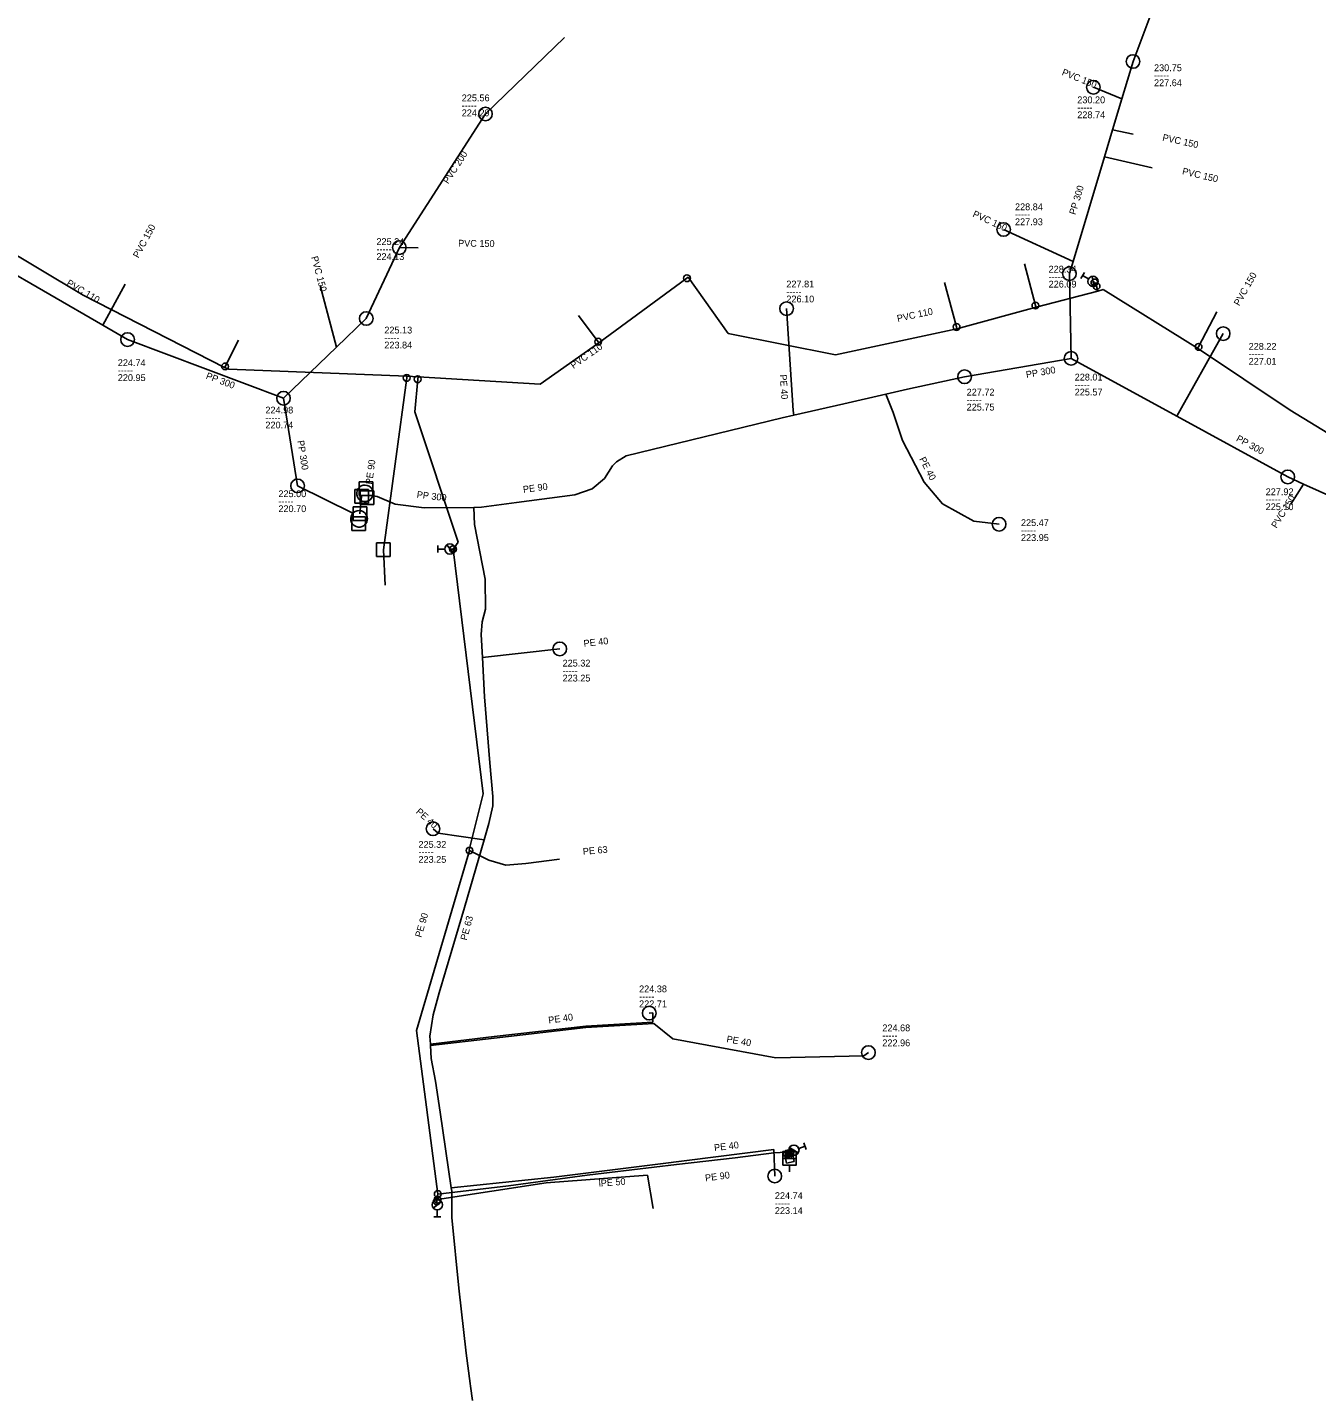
# Model space of a CAD drawing. Extents: x -771542 to -770341, y -1050442 to -1049881.
# Drawn here: x -770940.3 to -770751, y -1050441.5 to -1050239.8 of the extents above; entities that cross this region are included whole.
import ezdxf

# ---------------------------------------------------------------- set-up
doc = ezdxf.new("R2010")
doc.units = 0
doc.layers.add('Level 0', color=7, linetype='Continuous')

msp = doc.modelspace()

# ---------------------------------------------------------------- linework, layer by layer
at = {"layer": 'Level 0'}
for p, q in [((-770775.11, -1050237.31), (-770777.92, -1050244.75)), ((-770873.03, -1050252.46), (-770861.42, -1050241.24)), ((-770777.92, -1050244.75), (-770779.56, -1050250.23)), ((-770779.56, -1050250.23), (-770783.75, -1050248.53)), ((-770779.56, -1050250.23), (-770780.93, -1050254.79)), ((-770873.03, -1050252.46), (-770885.68, -1050272.1)), ((-770971.95, -1050255.18), (-770932.14, -1050279.1)), ((-770780.93, -1050254.79), (-770782.12, -1050258.77)), ((-770780.93, -1050254.79), (-770777.92, -1050255.44)), ((-770782.12, -1050258.77), (-770786.73, -1050274.16)), ((-770782.12, -1050258.77), (-770775.1, -1050260.4)), ((-770786.73, -1050274.16), (-770796.93, -1050269.44)), ((-770948.76, -1050272.21), (-770929.23, -1050283.51)), ((-770885.68, -1050272.1), (-770890.55, -1050282.52)), ((-770885.68, -1050272.1), (-770882.93, -1050272.13)), ((-770792.26, -1050280.61), (-770793.88, -1050274.5)), ((-770786.73, -1050274.16), (-770787.26, -1050275.93)), ((-770929.23, -1050283.51), (-770925.95, -1050277.46)), ((-770894.93, -1050286.74), (-770897.33, -1050277.68)), ((-770843.44, -1050276.6), (-770856.36, -1050286.09)), ((-770843.24, -1050276.45), (-770843.44, -1050276.6)), ((-770837.37, -1050284.72), (-770843.24, -1050276.45)), ((-770803.84, -1050283.76), (-770805.6, -1050277.24)), ((-770787.26, -1050275.93), (-770787.03, -1050288.38)), ((-770785.57, -1050276.62), (-770785.07, -1050275.75)), ((-770784.45, -1050276.69), (-770785.32, -1050276.19)), ((-770783.69, -1050277.8), (-770783.91, -1050276.32)), ((-770783.8, -1050277.06), (-770783.59, -1050277.22)), ((-770783.59, -1050277.22), (-770783.28, -1050277.78)), ((-770932.14, -1050279.1), (-770911.37, -1050289.74)), ((-770783.09, -1050278.48), (-770792.17, -1050280.85)), ((-770783.28, -1050277.78), (-770783.09, -1050278.48)), ((-770782.33, -1050278.28), (-770783.09, -1050278.48)), ((-770768.47, -1050286.88), (-770782.33, -1050278.28)), ((-770828.67, -1050283.24), (-770828.81, -1050281.07)), ((-770792.17, -1050280.85), (-770803.78, -1050284.02)), ((-770792.17, -1050280.85), (-770792.26, -1050280.61)), ((-770768.3, -1050286.69), (-770765.63, -1050281.52)), ((-770929.23, -1050283.51), (-770925.6, -1050285.61)), ((-770890.55, -1050282.52), (-770894.93, -1050286.74)), ((-770856.48, -1050285.93), (-770859.37, -1050282.07)), ((-770827.86, -1050296.04), (-770828.67, -1050283.24)), ((-770925.6, -1050285.61), (-770902.7, -1050294.23)), ((-770911.28, -1050289.56), (-770909.32, -1050285.69)), ((-770821.6, -1050287.84), (-770837.37, -1050284.72)), ((-770803.78, -1050284.02), (-770821.6, -1050287.84)), ((-770803.78, -1050284.02), (-770803.84, -1050283.76)), ((-770771.51, -1050296.87), (-770764.68, -1050284.74)), ((-770894.93, -1050286.74), (-770902.7, -1050294.23)), ((-770856.36, -1050286.09), (-770865.02, -1050292.18)), ((-770856.36, -1050286.09), (-770856.48, -1050285.93)), ((-770768.47, -1050286.88), (-770768.3, -1050286.69)), ((-770754.83, -1050296.01), (-770768.47, -1050286.88)), ((-770911.37, -1050289.74), (-770911.28, -1050289.56)), ((-770911.37, -1050289.74), (-770910.71, -1050289.96)), ((-770802.67, -1050291.08), (-770787.03, -1050288.38)), ((-770787.03, -1050288.38), (-770771.51, -1050296.87)), ((-770910.71, -1050289.96), (-770884.6, -1050290.99)), ((-770884.6, -1050291.25), (-770888.02, -1050316.5)), ((-770884.6, -1050290.99), (-770884.6, -1050291.25)), ((-770884.6, -1050290.99), (-770882.93, -1050291.09)), ((-770882.99, -1050291.44), (-770883.43, -1050296.23)), ((-770882.93, -1050291.09), (-770882.99, -1050291.44)), ((-770865.02, -1050292.18), (-770882.93, -1050291.09)), ((-770811.05, -1050292.89), (-770802.67, -1050291.08)), ((-770820.42, -1050295.05), (-770814.21, -1050293.62)), ((-770814.21, -1050293.62), (-770811.05, -1050292.89)), ((-770813.13, -1050296.32), (-770814.21, -1050293.62)), ((-770902.7, -1050294.23), (-770900.64, -1050307.11)), ((-770827.72, -1050296.72), (-770820.42, -1050295.05)), ((-770883.43, -1050296.23), (-770877.05, -1050315.4)), ((-770852.35, -1050302.69), (-770829.48, -1050297.12)), ((-770829.48, -1050297.12), (-770827.72, -1050296.72)), ((-770827.72, -1050296.72), (-770827.86, -1050296.04)), ((-770811.78, -1050300.44), (-770813.13, -1050296.32)), ((-770771.51, -1050296.87), (-770755.19, -1050305.8)), ((-770727.47, -1050312.73), (-770754.83, -1050296.01)), ((-770808.61, -1050306.59), (-770811.78, -1050300.44)), ((-770854.38, -1050304.17), (-770853.77, -1050303.58)), ((-770853.77, -1050303.58), (-770852.35, -1050302.69)), ((-770855.53, -1050306.02), (-770854.38, -1050304.17)), ((-770755.19, -1050305.8), (-770752.89, -1050306.84)), ((-770900.64, -1050307.11), (-770892.51, -1050311.14)), ((-770890.23, -1050307.66), (-770892.23, -1050307.66)), ((-770892.23, -1050307.66), (-770892.23, -1050309.66)), ((-770891.89, -1050307.82), (-770891.95, -1050308.13)), ((-770891.76, -1050307.54), (-770891.89, -1050307.82)), ((-770891.56, -1050307.3), (-770891.76, -1050307.54)), ((-770889.6, -1050306.53), (-770891.6, -1050306.53)), ((-770891.6, -1050306.53), (-770891.6, -1050308.53)), ((-770891.3, -1050307.13), (-770891.56, -1050307.3)), ((-770889.45, -1050307.84), (-770891.45, -1050307.84)), ((-770891.45, -1050307.84), (-770891.45, -1050309.84)), ((-770891.01, -1050307.02), (-770891.3, -1050307.13)), ((-770890.7, -1050306.99), (-770891.01, -1050307.02)), ((-770890.39, -1050307.04), (-770890.7, -1050306.99)), ((-770890.1, -1050307.17), (-770890.39, -1050307.04)), ((-770890.23, -1050309.66), (-770890.23, -1050307.66)), ((-770889.86, -1050307.36), (-770890.1, -1050307.17)), ((-770889.67, -1050307.61), (-770889.86, -1050307.36)), ((-770889.56, -1050307.9), (-770889.67, -1050307.61)), ((-770889.6, -1050308.53), (-770889.6, -1050306.53)), ((-770889.52, -1050308.21), (-770889.56, -1050307.9)), ((-770889.45, -1050309.84), (-770889.45, -1050307.84)), ((-770859.9, -1050308.42), (-770857.38, -1050307.53)), ((-770857.38, -1050307.53), (-770855.53, -1050306.02)), ((-770805.89, -1050309.75), (-770808.61, -1050306.59)), ((-770752.89, -1050306.84), (-770754.72, -1050309.79)), ((-770752.89, -1050306.84), (-770738.6, -1050313.34)), ((-770892.23, -1050309.66), (-770890.23, -1050309.66)), ((-770891.95, -1050308.13), (-770891.93, -1050308.44)), ((-770891.93, -1050308.44), (-770891.84, -1050308.74)), ((-770891.84, -1050308.74), (-770891.67, -1050309)), ((-770891.67, -1050309), (-770891.44, -1050309.21)), ((-770891.6, -1050308.53), (-770889.6, -1050308.53)), ((-770891.47, -1050311.21), (-770891.23, -1050308.66)), ((-770891.45, -1050309.84), (-770889.45, -1050309.84)), ((-770891.44, -1050309.21), (-770891.16, -1050309.35)), ((-770891.16, -1050309.35), (-770890.86, -1050309.42)), ((-770890.86, -1050309.42), (-770890.55, -1050309.41)), ((-770890.55, -1050309.41), (-770890.25, -1050309.32)), ((-770890.25, -1050309.32), (-770889.98, -1050309.16)), ((-770889.98, -1050309.16), (-770889.76, -1050308.94)), ((-770889.76, -1050308.53), (-770888.96, -1050308.68)), ((-770889.76, -1050308.94), (-770889.61, -1050308.67)), ((-770889.61, -1050308.67), (-770889.53, -1050308.37)), ((-770889.53, -1050308.37), (-770889.52, -1050308.21)), ((-770888.96, -1050308.68), (-770886.31, -1050309.82)), ((-770886.31, -1050309.82), (-770882.06, -1050310.32)), ((-770873.64, -1050310.22), (-770868.47, -1050309.54)), ((-770868.47, -1050309.54), (-770859.9, -1050308.42)), ((-770801.32, -1050312.29), (-770805.89, -1050309.75)), ((-770892.77, -1050311.56), (-770892.83, -1050311.87)), ((-770892.83, -1050311.87), (-770892.81, -1050312.18)), ((-770892.63, -1050311.28), (-770892.77, -1050311.56)), ((-770890.68, -1050311.65), (-770892.68, -1050311.65)), ((-770892.68, -1050311.65), (-770892.68, -1050313.65)), ((-770892.42, -1050311.05), (-770892.63, -1050311.28)), ((-770890.47, -1050310.21), (-770892.47, -1050310.21)), ((-770892.47, -1050310.21), (-770892.47, -1050312.21)), ((-770892.17, -1050310.87), (-770892.42, -1050311.05)), ((-770891.87, -1050310.76), (-770892.17, -1050310.87)), ((-770891.56, -1050310.74), (-770891.87, -1050310.76)), ((-770891.25, -1050310.79), (-770891.56, -1050310.74)), ((-770890.97, -1050310.91), (-770891.25, -1050310.79)), ((-770890.72, -1050311.11), (-770890.97, -1050310.91)), ((-770890.54, -1050311.36), (-770890.72, -1050311.11)), ((-770890.68, -1050313.65), (-770890.68, -1050311.65)), ((-770890.42, -1050311.65), (-770890.54, -1050311.36)), ((-770890.47, -1050312.21), (-770890.47, -1050310.21)), ((-770890.38, -1050311.96), (-770890.42, -1050311.65)), ((-770890.39, -1050312.14), (-770890.38, -1050311.96)), ((-770882.06, -1050310.32), (-770874.75, -1050310.3)), ((-770874.75, -1050310.3), (-770873.64, -1050310.22)), ((-770874.65, -1050312.8), (-770874.75, -1050310.3)), ((-770892.81, -1050312.18), (-770892.72, -1050312.48)), ((-770892.72, -1050312.48), (-770892.55, -1050312.74)), ((-770892.68, -1050313.65), (-770890.68, -1050313.65)), ((-770892.55, -1050312.74), (-770892.32, -1050312.96)), ((-770892.47, -1050312.21), (-770890.47, -1050312.21)), ((-770892.32, -1050312.96), (-770892.05, -1050313.1)), ((-770892.05, -1050313.1), (-770891.74, -1050313.18)), ((-770891.74, -1050313.18), (-770891.43, -1050313.17)), ((-770891.43, -1050313.17), (-770891.13, -1050313.09)), ((-770891.13, -1050313.09), (-770890.86, -1050312.93)), ((-770890.86, -1050312.93), (-770890.64, -1050312.71)), ((-770890.64, -1050312.71), (-770890.48, -1050312.44)), ((-770890.48, -1050312.44), (-770890.39, -1050312.14)), ((-770873.1, -1050320.84), (-770874.65, -1050312.8)), ((-770797.59, -1050312.75), (-770801.32, -1050312.29)), ((-770887.02, -1050315.5), (-770889.02, -1050315.5)), ((-770889.02, -1050315.5), (-770889.02, -1050317.5)), ((-770887.02, -1050317.5), (-770887.02, -1050315.5)), ((-770880.01, -1050316.89), (-770880.01, -1050315.89)), ((-770877.8, -1050316.98), (-770878.72, -1050315.8)), ((-770877.05, -1050315.4), (-770877.8, -1050316.42)), ((-770889.02, -1050317.5), (-770887.02, -1050317.5)), ((-770888.02, -1050316.5), (-770887.79, -1050321.68)), ((-770879.01, -1050316.39), (-770880.01, -1050316.39)), ((-770877.8, -1050316.42), (-770878.26, -1050316.39)), ((-770877.8, -1050316.42), (-770873.36, -1050352.39)), ((-770873.04, -1050325.23), (-770873.1, -1050320.84)), ((-770873.53, -1050327.07), (-770873.04, -1050325.23)), ((-770873.65, -1050328.95), (-770873.53, -1050327.07)), ((-770873.47, -1050332.35), (-770873.65, -1050328.95)), ((-770873.47, -1050332.35), (-770862.12, -1050331.07)), ((-770873.17, -1050338.09), (-770873.47, -1050332.35)), ((-770872.39, -1050347.81), (-770873.17, -1050338.09)), ((-770871.95, -1050352.75), (-770872.39, -1050347.81)), ((-770873.36, -1050352.39), (-770875.44, -1050360.6)), ((-770872.54, -1050356.71), (-770871.94, -1050354.15)), ((-770871.94, -1050354.15), (-770871.95, -1050352.75)), ((-770880, -1050358.16), (-770880.74, -1050357.5)), ((-770873.24, -1050359.13), (-770880, -1050358.16)), ((-770873.24, -1050359.13), (-770872.54, -1050356.71)), ((-770876.12, -1050369.07), (-770873.24, -1050359.13)), ((-770875.38, -1050360.69), (-770883.16, -1050387.13)), ((-770875.44, -1050360.6), (-770875.38, -1050360.69)), ((-770875.38, -1050360.69), (-770872.54, -1050362.13)), ((-770872.54, -1050362.13), (-770870.04, -1050362.87)), ((-770867.13, -1050362.61), (-770862.14, -1050361.99)), ((-770870.04, -1050362.87), (-770867.13, -1050362.61)), ((-770879.83, -1050381.61), (-770876.12, -1050369.07)), ((-770880.7, -1050384.86), (-770879.83, -1050381.61)), ((-770848.46, -1050384.57), (-770848.98, -1050384.59)), ((-770848.43, -1050385.94), (-770848.46, -1050384.57)), ((-770881.19, -1050388), (-770880.7, -1050384.86)), ((-770871.76, -1050388.05), (-770858.31, -1050386.52)), ((-770858.31, -1050386.52), (-770848.43, -1050385.94)), ((-770858.29, -1050386.72), (-770848.33, -1050386.13)), ((-770848.33, -1050386.13), (-770845.51, -1050388.37)), ((-770883.16, -1050387.13), (-770880.04, -1050411.18)), ((-770881.12, -1050389.16), (-770881.19, -1050388)), ((-770881.12, -1050389.16), (-770871.76, -1050388.05)), ((-770881.11, -1050389.36), (-770871.74, -1050388.25)), ((-770871.74, -1050388.25), (-770858.29, -1050386.72)), ((-770845.51, -1050388.37), (-770830.37, -1050391.18)), ((-770881.11, -1050389.36), (-770881.12, -1050389.16)), ((-770880.99, -1050391.24), (-770881.11, -1050389.36)), ((-770817.46, -1050390.85), (-770816.78, -1050390.39)), ((-770880.38, -1050394.58), (-770880.99, -1050391.24)), ((-770830.37, -1050391.18), (-770817.46, -1050390.85)), ((-770879.68, -1050399.16), (-770880.38, -1050394.58)), ((-770878.07, -1050410.27), (-770879.68, -1050399.16)), ((-770847.74, -1050406.8), (-770830.67, -1050404.65)), ((-770830.67, -1050404.65), (-770830.54, -1050408.53)), ((-770828.37, -1050404.35), (-770827.09, -1050405.14)), ((-770828.26, -1050404.93), (-770827.73, -1050404.74)), ((-770827.03, -1050404.48), (-770826.09, -1050404.14)), ((-770826.26, -1050403.67), (-770825.91, -1050404.61)), ((-770863.01, -1050408.7), (-770847.74, -1050406.8)), ((-770844.98, -1050406.84), (-770836.34, -1050405.86)), ((-770836.34, -1050405.86), (-770830.68, -1050405.1)), ((-770830.68, -1050405.1), (-770828.82, -1050405.03)), ((-770827.93, -1050405.23), (-770829.05, -1050405.45)), ((-770829.05, -1050405.45), (-770828.82, -1050406.63)), ((-770828.82, -1050405.03), (-770828.52, -1050404.99)), ((-770828.82, -1050405.03), (-770828.76, -1050405.26)), ((-770828.82, -1050406.63), (-770827.7, -1050406.41)), ((-770828.76, -1050405.26), (-770828.73, -1050405.96)), ((-770828.52, -1050404.99), (-770828.26, -1050404.93)), ((-770828.52, -1050404.99), (-770828.48, -1050405.17)), ((-770828.48, -1050405.17), (-770828.44, -1050405.94)), ((-770828.26, -1050404.93), (-770828.23, -1050405.14)), ((-770828.23, -1050405.14), (-770828.12, -1050405.92)), ((-770827.7, -1050406.41), (-770827.93, -1050405.23)), ((-770878.07, -1050410.27), (-770863.01, -1050408.7)), ((-770869.63, -1050409.98), (-770858.11, -1050408.4)), ((-770864.12, -1050409.55), (-770849.22, -1050408.42)), ((-770858.11, -1050408.4), (-770844.98, -1050406.84)), ((-770849.22, -1050408.42), (-770848.4, -1050413.28)), ((-770828.38, -1050407.93), (-770828.38, -1050406.93)), ((-770880.07, -1050412), (-770864.12, -1050409.55)), ((-770880.04, -1050411.18), (-770869.63, -1050409.98)), ((-770878, -1050410.74), (-770878.07, -1050410.27)), ((-770877.99, -1050414.61), (-770878, -1050410.74)), ((-770879.52, -1050412.31), (-770880.7, -1050413.23)), ((-770880.04, -1050411.18), (-770880.22, -1050411.99)), ((-770880.22, -1050411.99), (-770880.07, -1050412)), ((-770880.22, -1050411.99), (-770880.19, -1050412.27)), ((-770880.19, -1050412.27), (-770880.11, -1050412.77)), ((-770879.61, -1050414.52), (-770880.61, -1050414.52)), ((-770880.11, -1050413.52), (-770880.11, -1050414.52)), ((-770876.95, -1050424.99), (-770877.99, -1050414.61)), ((-770875.86, -1050434.55), (-770876.95, -1050424.99)), ((-770875.28, -1050439.02), (-770875.86, -1050434.55)), ((-770875.23, -1050439.39), (-770875.28, -1050439.02)), ((-770874.95, -1050441.52), (-770875.23, -1050439.39))]:
    msp.add_line(p, q, dxfattribs=at)
msp.add_lwpolyline([(-770829.38, -1050405.93), (-770829.38, -1050404.93), (-770827.38, -1050404.93), (-770827.38, -1050405.93)], dxfattribs=at)
msp.add_lwpolyline([(-770829.38, -1050406.93), (-770827.38, -1050406.93), (-770827.38, -1050405.93), (-770829.38, -1050405.93)], close=True, dxfattribs=at)
for centre, radius in [((-770777.92, -1050244.75), 1), ((-770783.75, -1050248.53), 1), ((-770873.03, -1050252.46), 1), ((-770796.93, -1050269.44), 1), ((-770885.68, -1050272.1), 1), ((-770787.26, -1050275.93), 1), ((-770843.44, -1050276.6), 0.5), ((-770783.8, -1050277.06), 0.75), ((-770783.59, -1050277.22), 0.5), ((-770783.28, -1050277.78), 0.5), ((-770890.55, -1050282.52), 1), ((-770828.81, -1050281.07), 1), ((-770792.26, -1050280.61), 0.5), ((-770803.84, -1050283.76), 0.5), ((-770764.68, -1050284.74), 1), ((-770925.6, -1050285.61), 1), ((-770856.48, -1050285.93), 0.5), ((-770787.03, -1050288.38), 1), ((-770768.3, -1050286.69), 0.5), ((-770911.28, -1050289.56), 0.5), ((-770884.6, -1050291.25), 0.5), ((-770882.99, -1050291.44), 0.5), ((-770802.67, -1050291.08), 1), ((-770902.7, -1050294.23), 1), ((-770755.19, -1050305.8), 1), ((-770900.64, -1050307.11), 1), ((-770797.59, -1050312.75), 1), ((-770878.26, -1050316.39), 0.75), ((-770877.8, -1050316.42), 0.5), ((-770862.12, -1050331.07), 1), ((-770880.74, -1050357.5), 1), ((-770875.38, -1050360.69), 0.5), ((-770848.98, -1050384.59), 1), ((-770816.78, -1050390.39), 1), ((-770828.76, -1050405.26), 0.5), ((-770828.48, -1050405.17), 0.5), ((-770828.23, -1050405.14), 0.5), ((-770827.73, -1050404.74), 0.75), ((-770830.54, -1050408.53), 1), ((-770880.04, -1050411.18), 0.5), ((-770880.11, -1050412.77), 0.75), ((-770880.19, -1050412.27), 0.5), ((-770880.07, -1050412), 0.5)]:
    msp.add_circle(centre, radius, dxfattribs=at)

# ---------------------------------------------------------------- texts
for s, p in [('230.75', (-770774.84, -1050246.18)), ('-----', (-770774.84, -1050247.28)), ('227.64', (-770774.84, -1050248.38)), ('-----', (-770876.52, -1050251.7)), ('225.56', (-770876.52, -1050250.6)), ('230.20', (-770786.11, -1050250.89)), ('224.29', (-770876.52, -1050252.8)), ('-----', (-770786.11, -1050251.99)), ('228.74', (-770786.11, -1050253.09)), ('-----', (-770795.26, -1050267.71)), ('228.84', (-770795.26, -1050266.61)), ('227.93', (-770795.26, -1050268.81)), ('225.24', (-770889.05, -1050271.72)), ('-----', (-770889.05, -1050272.82)), ('224.13', (-770889.05, -1050273.92)), ('228.34', (-770790.32, -1050275.77)), ('227.81', (-770828.84, -1050277.95)), ('-----', (-770790.32, -1050276.87)), ('226.09', (-770790.32, -1050277.97)), ('-----', (-770828.84, -1050279.05)), ('226.10', (-770828.84, -1050280.15)), ('225.13', (-770887.89, -1050284.72)), ('-----', (-770887.89, -1050285.82)), ('223.84', (-770887.89, -1050286.92)), ('-----', (-770760.94, -1050288.21)), ('228.22', (-770760.94, -1050287.11)), ('224.74', (-770927.04, -1050289.51)), ('227.01', (-770760.94, -1050289.31)), ('-----', (-770927.04, -1050290.61)), ('220.95', (-770927.04, -1050291.71)), ('228.01', (-770786.49, -1050291.63)), ('227.72', (-770802.36, -1050293.84)), ('-----', (-770786.49, -1050292.73)), ('225.57', (-770786.49, -1050293.83)), ('224.98', (-770905.36, -1050296.47)), ('-----', (-770802.36, -1050294.94)), ('225.75', (-770802.36, -1050296.04)), ('-----', (-770905.36, -1050297.57)), ('220.74', (-770905.36, -1050298.67)), ('225.00', (-770903.45, -1050308.77)), ('227.92', (-770758.44, -1050308.48)), ('-----', (-770903.45, -1050309.87)), ('220.70', (-770903.45, -1050310.97)), ('-----', (-770758.44, -1050309.58)), ('225.10', (-770758.44, -1050310.68)), ('-----', (-770794.38, -1050314.12)), ('225.47', (-770794.38, -1050313.02)), ('223.95', (-770794.38, -1050315.22)), ('225.32', (-770861.71, -1050333.66)), ('-----', (-770861.71, -1050334.76)), ('223.25', (-770861.71, -1050335.86)), ('225.32', (-770882.88, -1050360.3)), ('-----', (-770882.88, -1050361.4)), ('223.25', (-770882.88, -1050362.5)), ('224.38', (-770850.47, -1050381.53)), ('-----', (-770850.47, -1050382.63)), ('222.71', (-770850.47, -1050383.73)), ('224.68', (-770814.74, -1050387.26)), ('-----', (-770814.74, -1050388.36)), ('222.96', (-770814.74, -1050389.46)), ('-----', (-770830.53, -1050413.01)), ('224.74', (-770830.53, -1050411.91)), ('223.14', (-770830.53, -1050414.11))]:
    msp.add_text(s, height=1, dxfattribs=at).set_placement(p)
for s, rotation, p in [('PVC 150', 337.916, (-770788.46, -1050246.7)), ('PVC 150', 347.814, (-770773.67, -1050256.37)), ('PVC 200', 57.215, (-770878.51, -1050262.82)), ('PVC 150', 346.928, (-770770.77, -1050261.32)), ('PP 300', 73.354, (-770786.38, -1050267.35)), ('PVC 150', 335.168, (-770801.57, -1050267.51)), ('PVC 150', 61.536, (-770924, -1050273.72)), ('PVC 150', 359.375, (-770877.05, -1050271.95)), ('PVC 150', 284.837, (-770898.64, -1050273.5)), ('PVC 110', 329.255, (-770934.66, -1050277.58)), ('PVC 150', 60.618, (-770762.32, -1050280.75)), ('PVC 110', 12.002, (-770812.48, -1050283.02)), ('PVC 110', 35.116, (-770860.11, -1050289.95)), ('PP 300', 9.795, (-770793.56, -1050291.27)), ('PP 300', 339.373, (-770914.18, -1050291.33)), ('PE 40', 273.621, (-770829.8, -1050290.78)), ('PP 300', 331.313, (-770762.87, -1050300.46)), ('PP 300', 279.087, (-770900.68, -1050300.51)), ('PE 90', 82.286, (-770889.68, -1050306.95)), ('PE 40', 297.269, (-770809.35, -1050303.17)), ('PP 300', 353.29, (-770883.17, -1050308.86)), ('PE 90', 7.259, (-770867.46, -1050308.14)), ('PVC 150', 58.187, (-770756.85, -1050313.42)), ('PE 40', 6.434, (-770858.57, -1050330.77)), ('PE 40', 318.27, (-770883.33, -1050355.11)), ('PE 63', 5.106, (-770858.69, -1050361.34)), ('PE 90', 73.775, (-770882.45, -1050373.54)), ('PE 63', 75.014, (-770875.78, -1050373.97)), ('PE 40', 7.957, (-770863.73, -1050386.14)), ('PE 40', 350.189, (-770837.69, -1050388.86)), ('PE 40', 7.179, (-770839.39, -1050404.88)), ('lPE 50', 4.337, (-770856.36, -1050410.1)), ('PE 90', 7.648, (-770840.71, -1050409.33))]:
    msp.add_text(s, height=1, rotation=rotation, dxfattribs=at).set_placement(p)

doc.saveas('drawing.dxf')
